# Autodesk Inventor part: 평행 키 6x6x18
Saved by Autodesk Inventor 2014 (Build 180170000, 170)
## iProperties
Created: 2026-05
Part Number: 평행 키 6x6x18
Material: 일반
Document SubType Name: Modeling
Designer: dg
Density: 1 g/cm^3
Appearance: 기본값
Author: dg
Author: jhkim
Description: 키 및 해당 키홈
Creation Date: 2026-04-23
Sending System: Autodesk Inventor 2027
Preprocessor: ST-DEVELOPER v20.1
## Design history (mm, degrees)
node "평행 키 6x6x181"
body "Solid1"
node "기준1"
